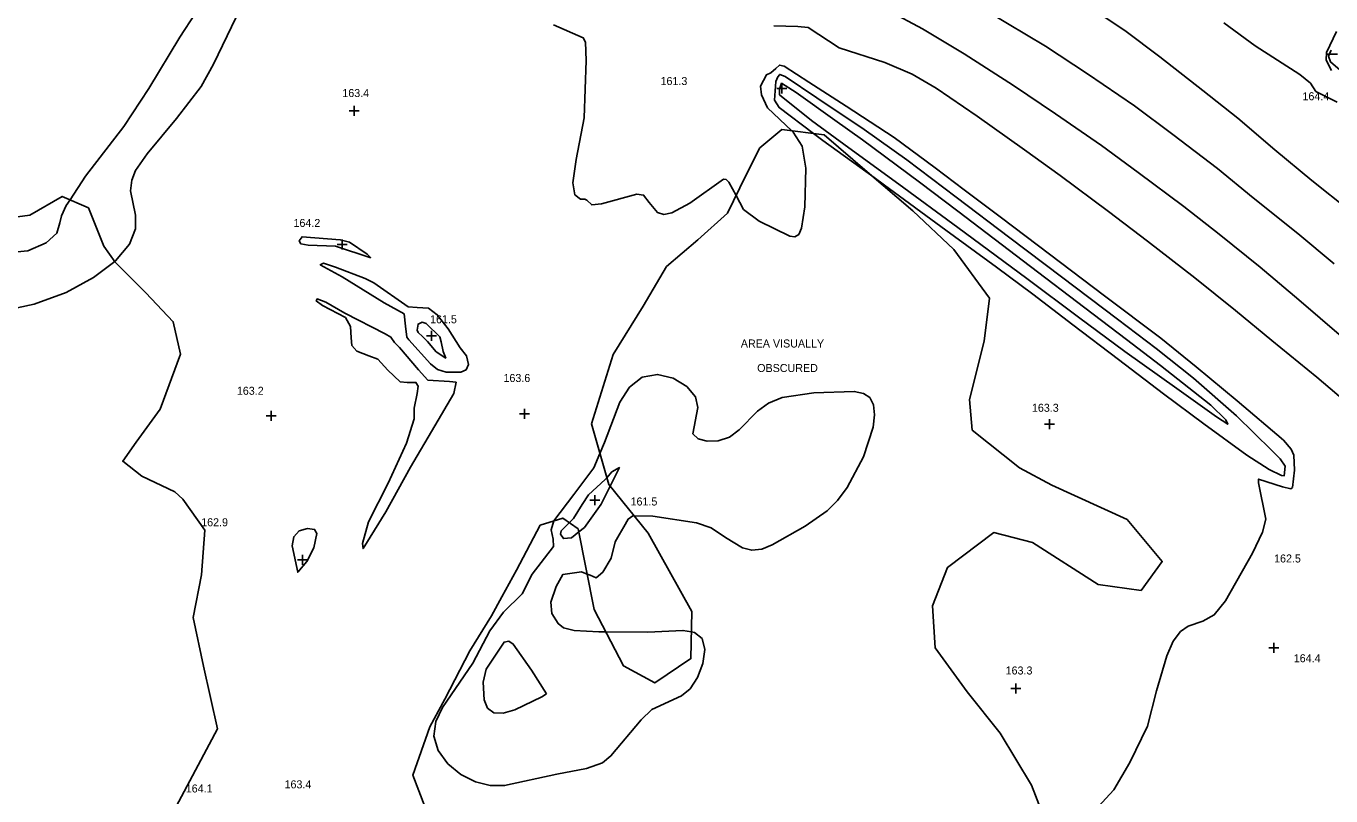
# Model space of a CAD drawing. Extents: x 1475150 to 2003689, y 770235 to 1112803.
# Drawn here: x 1998713.9 to 1999039.9, y 775230.1 to 775422.4 of the extents above; entities that cross this region are included whole.
import ezdxf

# ---------------------------------------------------------------- set-up
doc = ezdxf.new("R2010")
doc.units = 0
for name, color, linetype in [('RD_DTM_Major1', 7, 'Continuous'), ('RD_DTM_Major2', 7, 'Continuous'), ('RD_DTM_Minor1', 7, 'Continuous'), ('RD_DTM_Minor2', 7, 'Continuous'), ('RD_DTM_Obscure', 7, 'Continuous'), ('RD_DTM_Spot_Elev', 7, 'Continuous'), ('RD_TX_Misc1', 7, 'Continuous')]:
    doc.layers.add(name, color=color, linetype=linetype)

msp = doc.modelspace()

# ---------------------------------------------------------------- linework, layer by layer
at = {"layer": 'RD_DTM_Major1'}
for points in [[(1998724.83, 775379), (1998728.72, 775384.88), (1998738.28, 775397.31), (1998744.56, 775406.83), (1998752.27, 775419.6), (1998756.21, 775425.63), (1998761.97, 775432.34), (1998764.58, 775436.68), (1998769.9, 775447.76), (1998772.18, 775452.02), (1998774.86, 775455.09), (1998778.26, 775457.02), (1998790.11, 775461), (1998795.53, 775463.5), (1998799.54, 775466.03), (1998803.87, 775464.29), (1998809.57, 775462.01), (1998811.74, 775461.51)], [(1998900.66, 775422.42), (1998906.69, 775422.32), (1998909.27, 775422.06), (1998917.04, 775416.98), (1998928.4, 775413.25), (1998935.24, 775410.36), (1998941.27, 775406.91), (1998951.44, 775399.88), (1998963.29, 775391.48), (1998972.2, 775385.07), (1998984.27, 775376.05), (1998994.05, 775368.65), (1999005.86, 775359.46), (1999016.05, 775351.35), (1999025.09, 775343.81), (1999036.38, 775334.67), (1999045.22, 775327.07)]]:
    msp.add_lwpolyline(points, dxfattribs=at)
at = {"layer": 'RD_DTM_Major2'}
msp.add_lwpolyline([(1998631.47, 775366.46), (1998637.38, 775366.21), (1998648.63, 775369.05), (1998661.12, 775372.22), (1998664.89, 775372.74), (1998669.03, 775372.8), (1998673.95, 775372.29), (1998686.5, 775369.67), (1998699.14, 775366.79), (1998708.16, 775365.62), (1998714.28, 775366.25), (1998718.88, 775368.23), (1998721.57, 775370.69), (1998722.28, 775373.22), (1998722.74, 775375.01), (1998723.86, 775377.54), (1998724.83, 775379)], dxfattribs=at)
at = {"layer": 'RD_DTM_Minor1'}
for points in [[(1998976.55, 775429.22), (1998988.34, 775421.3), (1998997.09, 775414.73), (1999007.84, 775406.29), (1999016.57, 775399.36), (1999025.82, 775391.51), (1999035.13, 775383.77), (1999044.5, 775376.35)], [(1998929.43, 775426.19), (1998937.85, 775421.68), (1998948.26, 775415.47), (1998960.56, 775407.52), (1998971.04, 775400.45), (1998982.53, 775392.54), (1998991.72, 775385.78), (1999003.11, 775377.32), (1999011.92, 775370.4), (1999022.19, 775362.18), (1999031.83, 775353.97), (1999042.54, 775344.87)], [(1998736.02, 775363.61), (1998736.18, 775363.73), (1998739.73, 775367.88), (1998741.2, 775371.71), (1998741.18, 775375.19), (1998739.97, 775381.25), (1998740.24, 775383.9), (1998741.2, 775386.33), (1998744.1, 775390.5), (1998751.45, 775399.33), (1998757.6, 775407.3), (1998760.7, 775412.85), (1998766.34, 775424.6)], [(1998954.31, 775425.85), (1998968.55, 775417.33), (1998979.02, 775410.5), (1998990.8, 775402.43), (1999000.34, 775395.27), (1999011.51, 775386.81), (1999020.45, 775379.52), (1999031.56, 775370.6), (1999040.71, 775363)], [(1999041.39, 775403.39), (1999036.07, 775406.06), (1999034.73, 775408.16), (1999032.08, 775410.28), (1999020.95, 775417.43), (1999013.13, 775423.19)], [(1998845.66, 775422.66), (1998853.05, 775419.47), (1998853.63, 775418.34), (1998853.81, 775413.8), (1998853.25, 775399.5), (1998851.25, 775389.06), (1998850.44, 775383.21), (1998850.92, 775380.27), (1998852.35, 775379.16), (1998853.47, 775379.14), (1998853.92, 775378.93), (1998855.18, 775377.73), (1998857.64, 775377.96), (1998866.42, 775380.41), (1998868.13, 775380.15), (1998869.49, 775378.29), (1998871.6, 775375.84), (1998873.18, 775375.33), (1998875.18, 775375.71), (1998879.69, 775378.18), (1998888.06, 775384.16), (1998888.79, 775384.05), (1998889.46, 775383.39), (1998891.24, 775380.07)], [(1999040.04, 775411.27), (1999038.7, 775413.84), (1999038.73, 775415.76), (1999041.22, 775421.07)], [(1999049.24, 775405.3), (1999039.72, 775413.43), (1999039.27, 775414.86), (1999039.91, 775416.41)], [(1998905.2, 775396.22), (1998899.08, 775401.94), (1998897.58, 775405.2), (1998897.35, 775407.36), (1998898.87, 775410.24), (1998899.9, 775410.75), (1998901.18, 775411.78), (1998902.09, 775412.64), (1998903.25, 775412.36), (1998909.39, 775408.4), (1998918.71, 775402.36), (1998930.7, 775394.56), (1998941.01, 775386.97), (1998948.26, 775381.49), (1998957.22, 775374.72), (1998966.76, 775367.51), (1998983.31, 775355.02), (1998997.34, 775344.44), (1999006.23, 775337.3), (1999016.44, 775328.73), (1999028, 775318.91), (1999029.96, 775316.73), (1999030.59, 775315.19), (1999030.72, 775311.44), (1999030.29, 775307.14), (1999029.87, 775306.82), (1999027.78, 775307.27), (1999021.79, 775309.2), (1999021.76, 775308.3), (1999023.6, 775299.17), (1999022.79, 775295.94), (1999020.29, 775290.74), (1999013.53, 775278.82), (1999010.69, 775275.3), (1999007.83, 775273.69), (1999004.21, 775272.47), (1999002.29, 775271.12), (1999000.46, 775268.72), (1998998.83, 775265.07), (1998996.3, 775256.3), (1998994.02, 775247.51), (1998989.58, 775238.39), (1998985.59, 775231.61), (1998981.69, 775227.31)], [(1998910.61, 775395.56), (1998902.05, 775402.01), (1998900.85, 775403.84), (1998901.2, 775408.58), (1998901.7, 775409.73), (1998902.17, 775410.3), (1998903.5, 775409.83), (1998911.45, 775404.49), (1998923.25, 775396.58), (1998933.87, 775388.98), (1998946.27, 775379.68), (1998959.67, 775369.51), (1998972.55, 775359.77), (1998986.54, 775349.21), (1998996.2, 775341.87), (1999005.56, 775334.45), (1999016.3, 775325.05), (1999025.1, 775316.34), (1999027.18, 775314.31), (1999028.4, 775312.45), (1999028.21, 775310.07), (1999027.51, 775310.11), (1999024.39, 775311.6), (1999018.85, 775315.16), (1999008.12, 775323.05), (1998998.04, 775330.55), (1998986.76, 775339.06), (1998975.41, 775347.77), (1998965.35, 775355.42), (1998956.31, 775362.14), (1998943.67, 775371.43), (1998928.31, 775382.67), (1998925.71, 775384.55)], [(1999011.28, 775324.8), (1999001.38, 775331.88), (1998988.37, 775341.13), (1998976.83, 775349.67), (1998963.87, 775359.31), (1998946.62, 775372.04), (1998931.89, 775382.88), (1998919.45, 775391.98), (1998910.08, 775398.83), (1998902.07, 775405.24), (1998902.08, 775406.59), (1998902.62, 775408.12), (1998906.23, 775405.77), (1998915.91, 775398.92), (1998922.83, 775394), (1998937.05, 775383.39), (1998946.65, 775376.11), (1998964.8, 775362.31), (1998978.35, 775352.02), (1998988.79, 775344.08), (1998997.26, 775337.56), (1999009.85, 775327.7), (1999013.62, 775323.99), (1999014.1, 775322.92), (1999011.28, 775324.8)], [(1998800.02, 775364.53), (1998799.04, 775365.43), (1998794.69, 775368.42), (1998792.34, 775369), (1998782.8, 775369.77), (1998782.12, 775368.77), (1998782.54, 775367.95), (1998784.37, 775367.62), (1998791.17, 775367.4), (1998800.02, 775364.53)], [(1998808.34, 775350.49), (1998803.36, 775353.26), (1998792.79, 775359.75), (1998787.35, 775362.78), (1998788.19, 775363.19), (1998791.15, 775362.17), (1998798.58, 775359.31), (1998800.76, 775358.28), (1998809.3, 775352.22), (1998811.6, 775352.06), (1998814.38, 775351.88), (1998816.6, 775350.27), (1998819.29, 775346.78), (1998822.27, 775342.01), (1998823.91, 775339.98), (1998824.42, 775337.84), (1998823.79, 775336.48), (1998822.44, 775335.95), (1998818.79, 775335.91), (1998816.61, 775336.61), (1998814.9, 775338.03), (1998809.47, 775344.02), (1998808.99, 775344.7), (1998808.61, 775347.43), (1998808.34, 775350.49)], [(1998803.54, 775345.5), (1998793.49, 775350.65), (1998788.76, 775353.45), (1998786.58, 775354.21), (1998786.36, 775353.74), (1998787.95, 775352.61), (1998793.68, 775349.55), (1998794.9, 775347.32), (1998795.09, 775344.49), (1998795.26, 775342.57), (1998796.46, 775341.14), (1998799.52, 775340.05), (1998801.77, 775339.2), (1998804.27, 775336.41), (1998807.32, 775333.55), (1998809.03, 775333.36), (1998811.26, 775333.35), (1998811.82, 775332.42), (1998811.56, 775330.59), (1998810.84, 775326.93), (1998810.82, 775324.27), (1998808.94, 775318.18), (1998804.35, 775308.21), (1998799.42, 775298.53), (1998797.93, 775293.09), (1998798.04, 775291.87), (1998803.75, 775301), (1998809.93, 775312.22), (1998816.01, 775322.56), (1998820.71, 775330.62), (1998821.3, 775333.4), (1998819.68, 775333.56), (1998814.24, 775333.97), (1998811.94, 775336.51), (1998807.19, 775342.13), (1998805.88, 775343.36), (1998805.02, 775344.7), (1998803.54, 775345.5)], [(1998811.83, 775345.84), (1998811.54, 775346.38), (1998811.78, 775347.96), (1998812.84, 775348.43), (1998813.85, 775348.06), (1998817.21, 775344.74), (1998817.6, 775343.48), (1998818.06, 775341.1), (1998818.72, 775339.44), (1998816.35, 775340.99), (1998814.15, 775343.56), (1998812.94, 775344.87), (1998811.83, 775345.84)], [(1998845.72, 775298.78), (1998845.72, 775298.79), (1998850.71, 775305.36), (1998855.73, 775312), (1998857.24, 775315.64)], [(1998849.58, 775298.33), (1998850.62, 775299.37), (1998852.83, 775302.83), (1998854.39, 775305.32), (1998858.57, 775309.12), (1998858.96, 775309.57)], [(1998859.77, 775307.48), (1998857.5, 775302.96), (1998853.39, 775297.15), (1998851.96, 775296.01)], [(1998865.74, 775300.03), (1998865.46, 775300.04), (1998864.29, 775299.22), (1998863.21, 775297.3), (1998862.07, 775295.28), (1998861.03, 775293.54), (1998860.01, 775289.48), (1998857.99, 775285.99), (1998856.31, 775284.56), (1998854.81, 775285.22), (1998854.05, 775285.5)], [(1998780.31, 775292.51), (1998780.73, 775294.81), (1998782.11, 775296.26), (1998784.19, 775296.88), (1998785.95, 775296.65), (1998786.48, 775295.63), (1998785.75, 775292.07), (1998783.98, 775288.61), (1998781.72, 775285.95), (1998780.31, 775292.51)], [(1998858.7, 775271.08), (1998869.2, 775271), (1998877.97, 775271.42), (1998880.07, 775271.04)]]:
    msp.add_lwpolyline(points, dxfattribs=at)
at = {"layer": 'RD_DTM_Minor2'}
for points in [[(1998891.24, 775380.07), (1998893.11, 775376.57), (1998896.99, 775373.67), (1998904.69, 775369.87), (1998905.94, 775369.73), (1998906.91, 775370.36), (1998907.61, 775371.93), (1998908.39, 775377.2), (1998908.64, 775386.89), (1998907.73, 775392.37), (1998905.53, 775395.9), (1998905.2, 775396.22)], [(1998925.71, 775384.55), (1998912.94, 775393.8), (1998910.61, 775395.56)], [(1998707.35, 775351.08), (1998715.89, 775352.92), (1998723.84, 775355.85), (1998730.74, 775359.58), (1998736.02, 775363.61)], [(1998857.24, 775315.64), (1998858.37, 775318.35), (1998862.2, 775328.4), (1998864.62, 775332.18), (1998867.76, 775334.72), (1998871.57, 775335.37), (1998875.51, 775334.41), (1998878.91, 775332.38), (1998881.1, 775329.8), (1998881.65, 775327.14), (1998880.47, 775320.55), (1998881.74, 775319.28), (1998884.01, 775318.66), (1998886.79, 775318.78), (1998889.57, 775319.73), (1998891.98, 775321.52), (1998896.56, 775326.17), (1998899.34, 775328.2), (1998902.77, 775329.57), (1998910.66, 775330.8), (1998920.78, 775331.1), (1998923.06, 775330.63), (1998924.68, 775329.56), (1998925.59, 775327.74), (1998925.84, 775325.25), (1998925.46, 775322.19), (1998923.08, 775314.81), (1998919.02, 775307.15), (1998916.59, 775303.89), (1998913.99, 775301.29), (1998908.51, 775297.48), (1998900.26, 775292.77), (1998897.65, 775291.75), (1998895.15, 775291.45), (1998892.81, 775292.01), (1998888.59, 775294.65), (1998885.02, 775297.04), (1998881.36, 775298.25), (1998870.42, 775299.94), (1998865.74, 775300.03)], [(1998858.96, 775309.57), (1998860.22, 775311.02), (1998862.09, 775312.1), (1998859.77, 775307.48)], [(1998880.07, 775271.04), (1998880.84, 775270.89), (1998882.81, 775269.37), (1998883.46, 775266.62), (1998882.96, 775263.15), (1998881.62, 775259.64), (1998879.75, 775256.8), (1998877.61, 775255.09), (1998870.21, 775251.63), (1998867.54, 775249.1), (1998859.97, 775240.05), (1998857.84, 775238.34), (1998853.84, 775236.94), (1998846.42, 775235.47), (1998833.39, 775232.64), (1998829.79, 775232.69), (1998826.12, 775233.55), (1998822.45, 775235.41), (1998819.19, 775238.11), (1998816.79, 775241.39), (1998815.72, 775245), (1998816.24, 775248.67), (1998817.89, 775252.16), (1998825.46, 775263.24), (1998829.68, 775271.28), (1998833.12, 775275.96), (1998837.78, 775280.59), (1998840.32, 775285.47), (1998845.59, 775292.37), (1998845.57, 775294.24), (1998845.03, 775296.52), (1998845.72, 775298.78)], [(1998851.96, 775296.01), (1998850.15, 775294.58), (1998848.12, 775294.37), (1998847.37, 775295.48), (1998847.55, 775296.27), (1998849.58, 775298.33)], [(1998854.05, 775285.5), (1998852.59, 775286.03), (1998847.98, 775285.41), (1998846.29, 775282.35), (1998844.99, 775278.44), (1998845.23, 775275.61), (1998846.78, 775273.12), (1998848.11, 775272.08), (1998850.82, 775271.43), (1998856.94, 775271.09), (1998858.7, 775271.08)], [(1998843.92, 775255.59), (1998842.7, 775254.86), (1998835.95, 775251.6), (1998833.09, 775250.78), (1998830.7, 775250.82), (1998829.13, 775252.02), (1998828.31, 775254.04), (1998828.05, 775258.5), (1998828.79, 775261.75), (1998833.3, 775268.48), (1998834.47, 775268.76), (1998835.57, 775268.01), (1998840.12, 775261.52), (1998843.92, 775255.59)]]:
    msp.add_lwpolyline(points, dxfattribs=at)
at = {"layer": 'RD_DTM_Obscure'}
for points in [[(1998813.49, 775227.39), (1998810.5, 775235.21), (1998814.73, 775247.3), (1998818.48, 775254.25), (1998824.72, 775266.31), (1998830.1, 775275.08), (1998832.76, 775279.8), (1998836.4, 775286.48), (1998842.3, 775297.7), (1998847.95, 775299.48), (1998851.81, 775296.77), (1998855.81, 775276.65), (1998863.12, 775262.56), (1998870.91, 775258.29), (1998879.96, 775264.36), (1998880.16, 775276.11), (1998869.24, 775295.67), (1998859.43, 775307.9), (1998855.14, 775323.06), (1998860.54, 775340.34), (1998868.02, 775352.43), (1998873.85, 775362.32), (1998881.7, 775368.95), (1998889.07, 775375.69), (1998893.72, 775385.08), (1998897.18, 775391.96), (1998902.7, 775396.52), (1998913.25, 775395.24), (1998924.01, 775386.01), (1998935.41, 775376.26), (1998945.66, 775366.58), (1998954.53, 775354.4), (1998953.24, 775343.66), (1998949.53, 775329.14), (1998950.23, 775321.45), (1998962.03, 775312.06), (1998970.11, 775307.67), (1998988.95, 775299.12), (1998997.73, 775288.66), (1998992.43, 775281.4), (1998981.7, 775282.88), (1998965.27, 775293.4), (1998955.66, 775295.87), (1998944.06, 775287.16), (1998940.34, 775277.52), (1998940.98, 775267.06), (1998948.96, 775256.07), (1998957.26, 775245.74), (1998965.03, 775232.76), (1998970.27, 775219.16)], [(1998707.31, 775374.19), (1998714.81, 775375.12), (1998722.9, 775379.83), (1998729.43, 775377), (1998733.3, 775367.42), (1998736.14, 775363.45), (1998743.75, 775355.77), (1998750.62, 775348.52), (1998752.47, 775340.39), (1998747.33, 775326.72), (1998741.34, 775318.44), (1998738.02, 775313.66), (1998742.78, 775309.96), (1998750.98, 775306.07), (1998752.98, 775304.24), (1998758.49, 775296.49), (1998757.68, 775285.26), (1998755.58, 775274.67), (1998758.16, 775262.5), (1998761.7, 775246.83)], [(1998761.7, 775246.83), (1998743.05, 775211.78), (1998726.04, 775182.17), (1998721.42, 775168.28), (1998715.96, 775150.05), (1998711.27, 775135.02)]]:
    msp.add_lwpolyline(points, dxfattribs=at)
at = {"layer": 'RD_DTM_Spot_Elev'}
for p, q in [((1999039.01, 775415.38), (1999041.51, 775415.38)), ((1998901.4, 775406.76), (1998903.9, 775406.76)), ((1998902.65, 775405.51), (1998902.65, 775408.01)), ((1998794.56, 775401.23), (1998797.06, 775401.23)), ((1998795.81, 775399.98), (1998795.81, 775402.48)), ((1998791.55, 775367.82), (1998794.05, 775367.82)), ((1998792.8, 775366.57), (1998792.8, 775369.07)), ((1998813.86, 775345.02), (1998816.36, 775345.02)), ((1998815.11, 775343.77), (1998815.11, 775346.27)), ((1998773.8, 775325.05), (1998776.3, 775325.05)), ((1998775.05, 775323.8), (1998775.05, 775326.3)), ((1998837.12, 775325.51), (1998839.62, 775325.51)), ((1998838.37, 775324.26), (1998838.37, 775326.76)), ((1998968.26, 775322.92), (1998970.76, 775322.92)), ((1998969.51, 775321.67), (1998969.51, 775324.17)), ((1998854.67, 775303.92), (1998857.17, 775303.92)), ((1998855.92, 775302.67), (1998855.92, 775305.17)), ((1998781.69, 775289.07), (1998784.19, 775289.07)), ((1998782.94, 775287.82), (1998782.94, 775290.32)), ((1999024.34, 775267.09), (1999026.84, 775267.09)), ((1999025.59, 775265.84), (1999025.59, 775268.34)), ((1998959.87, 775256.93), (1998962.37, 775256.93)), ((1998961.12, 775255.68), (1998961.12, 775258.18))]:
    msp.add_line(p, q, dxfattribs=at)

# ---------------------------------------------------------------- texts
for s, p in [('161.3', (1998872.37, 775407.66)), ('163.4', (1998792.87, 775404.66)), ('164.4', (1999032.75, 775403.86)), ('164.2', (1998780.67, 775372.21)), ('161.5', (1998814.79, 775348.14)), ('163.6', (1998833.13, 775333.47)), ('163.2', (1998766.52, 775330.28)), ('163.3', (1998965.16, 775326.03)), ('161.5', (1998864.88, 775302.62)), ('162.9', (1998757.61, 775297.43)), ('162.5', (1999025.66, 775288.38)), ('164.4', (1999030.57, 775263.46)), ('163.3', (1998958.59, 775260.4)), ('163.4', (1998778.43, 775231.96)), ('164.1', (1998753.75, 775230.92))]:
    msp.add_text(s, height=2, dxfattribs=at).set_placement(p)
at = {"layer": 'RD_TX_Misc1'}
for s, p in [('AREA VISUALLY', (1998892.43, 775342.09)), ('OBSCURED', (1998896.52, 775335.97))]:
    msp.add_text(s, height=2, dxfattribs=at).set_placement(p)

doc.saveas('drawing.dxf')
